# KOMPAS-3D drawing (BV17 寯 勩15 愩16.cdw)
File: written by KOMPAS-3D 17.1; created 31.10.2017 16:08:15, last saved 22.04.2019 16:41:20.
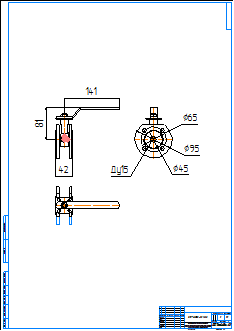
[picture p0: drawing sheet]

Sheet 1: A1, portrait

Title block, sheet 1: name: BV17 МФ Ду15 Ру16; material: Внимание! Данный продукт является объектом авторского права ООО «Торговый Дом АДЛ». / Запрещается изменение, копирование, распространение / (в том числе путем копирования на другие сайты и ресурсы в Интернете) / или любое иное использование информации и объектов без предварительного / согласия правообладателя (ООО «Торговый Дом АДЛ»).; mass: 1; sheets: 1; organisation: ООО "Торговый дом АДЛ"; sheet format: A1; stored path: \\adlc.lan\data\АДЛ_ПКД\3D-модели\ADL production\Краны шаровые серии BV\BV17 МФ Нержавеющие Ру16\KOMPAS 2D\BV17 МФ Ду15 Ру16.cdw

Views: Вид 1, Проекционный вид 2, Проекционный вид 3
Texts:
  kka
  adl
Dimensions and other numbers on the sheet: 42; 141; 81; 15; 95; 65; 45; 1:1; 1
